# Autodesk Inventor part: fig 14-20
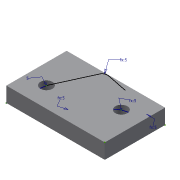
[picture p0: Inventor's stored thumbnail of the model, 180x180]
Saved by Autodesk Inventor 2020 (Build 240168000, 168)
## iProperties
Created: 2005-04
Part Number: fig 14-20
Document SubType Name: Modeling
Designer: CADCIM
Density: 1 g/cm^3
Material: Generic
Appearance: Default
Author: CADCIM
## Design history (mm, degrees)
sketch "Sketch1"
  geometry: L1 (-34.758, -22.218)-(30.545, -22.218); L2 (30.545, -22.218)-(30.545, 17.782); L3 (30.545, 17.782)-(-34.758, 17.782); L4 (-34.758, 17.782)-(-34.758, -22.218)
  constraints: 8 end point, 2 parallel, 1 horizontal, 1 perpendicular
  dimensions: "d0" = 65.30359 distance of L2.end L3.end; "d1" = 40 distance of L1.end L2.end
extrude "Extrusion1" new body sketch "Sketch1" distance "d2" = 10; taper "d3" = 0 deg
hole "Hole1" diameter "d13" = 8; stored, may be unused: countersink angle "d17" = 90 deg, drill point angle "d19" = 118 deg; dims "d11" = 13.458, "d12" = 13.14, "d14" = 6, "d15" = 4, "d16" = 2, "d18" = 15
hole "Hole2" diameter "d22" = 8; stored, may be unused: countersink angle "d26" = 90 deg, drill point angle "d28" = 118 deg; dims "d20" = 13.299, "d21" = 15.705, "d23" = 6, "d24" = 4, "d25" = 2, "d27" = 15
sketch "3D Sketch2" dims "d29" = 5, "d30" = 5 (= d29), "d31" = 5 (= d29), "d32" = 5 (= d29), "d33" = 5 (= d29)
body "Solid1"
other parameters: "LEN" = 1 [user parameter]
